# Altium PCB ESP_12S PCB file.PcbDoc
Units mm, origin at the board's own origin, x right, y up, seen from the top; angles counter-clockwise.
Board outline 16 x 24 mm, 4 copper layers (Top Layer, GND, Power, Bottom Layer), stack 0.778 mm thick; 37 components, 28 nets, 113 pads, 121 vias.
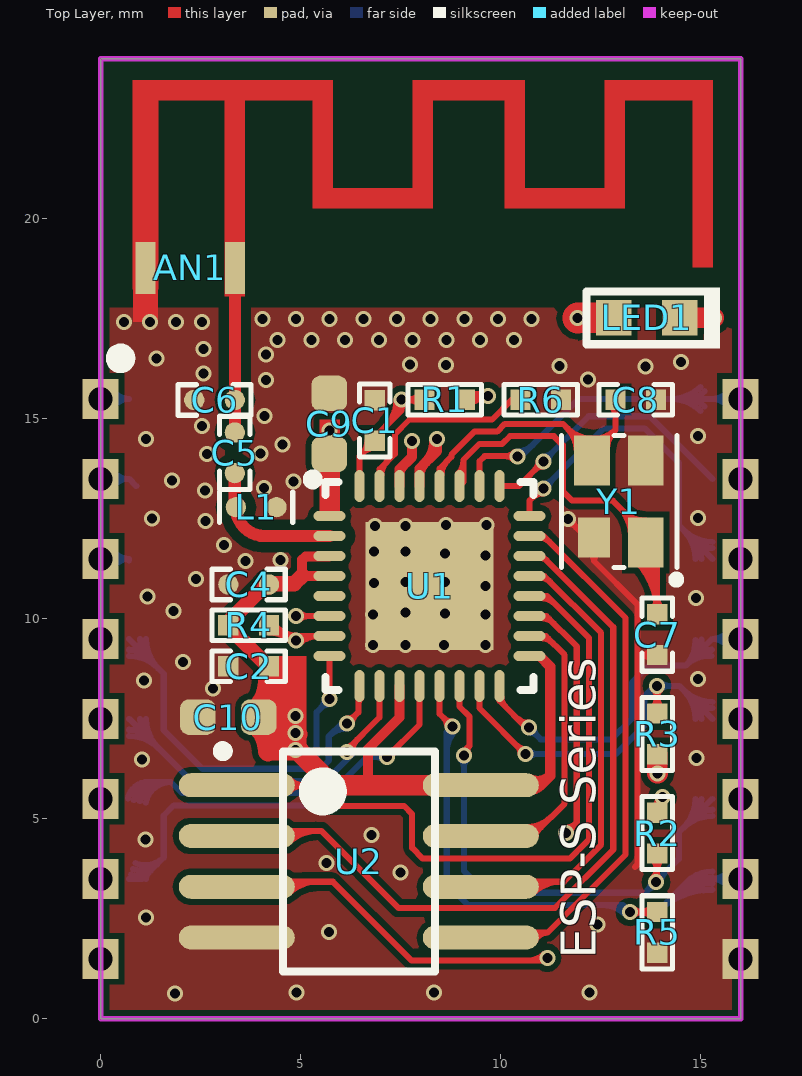
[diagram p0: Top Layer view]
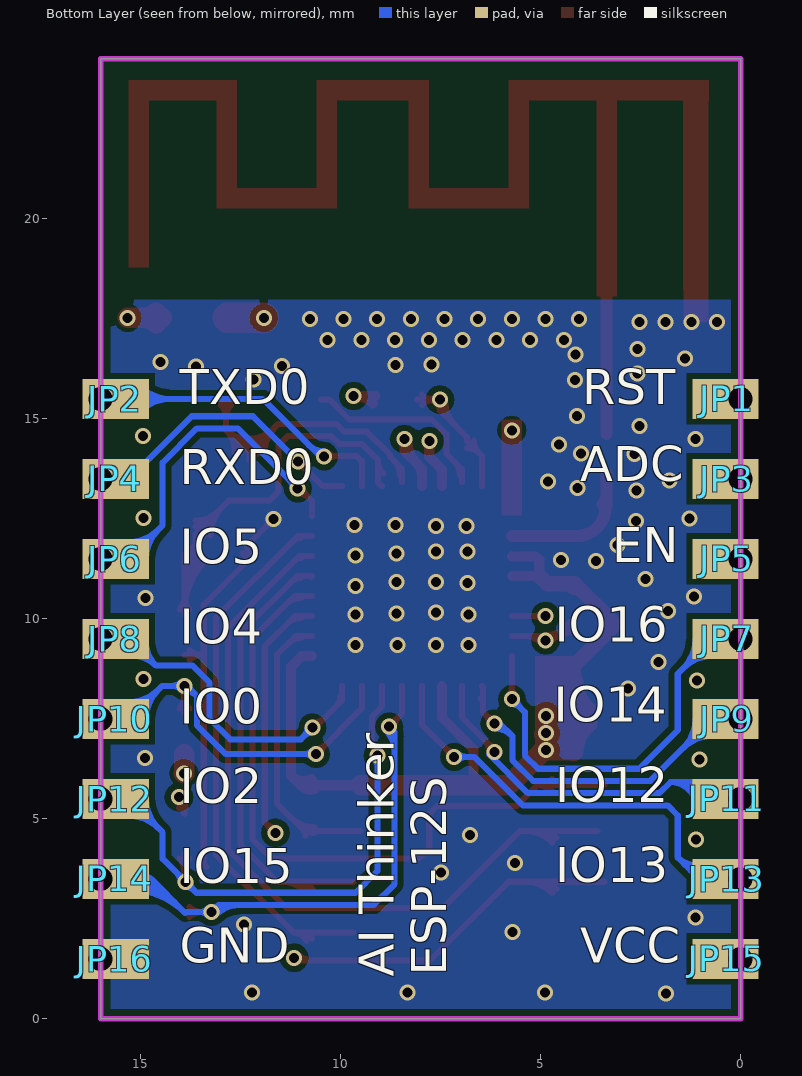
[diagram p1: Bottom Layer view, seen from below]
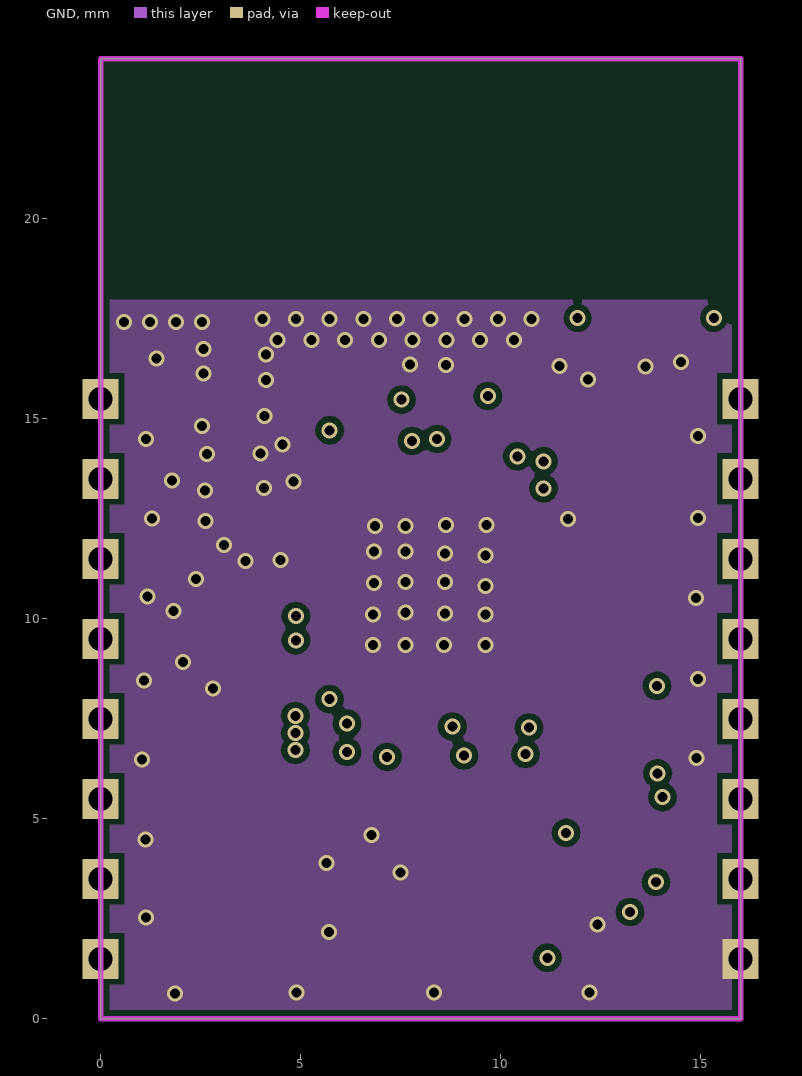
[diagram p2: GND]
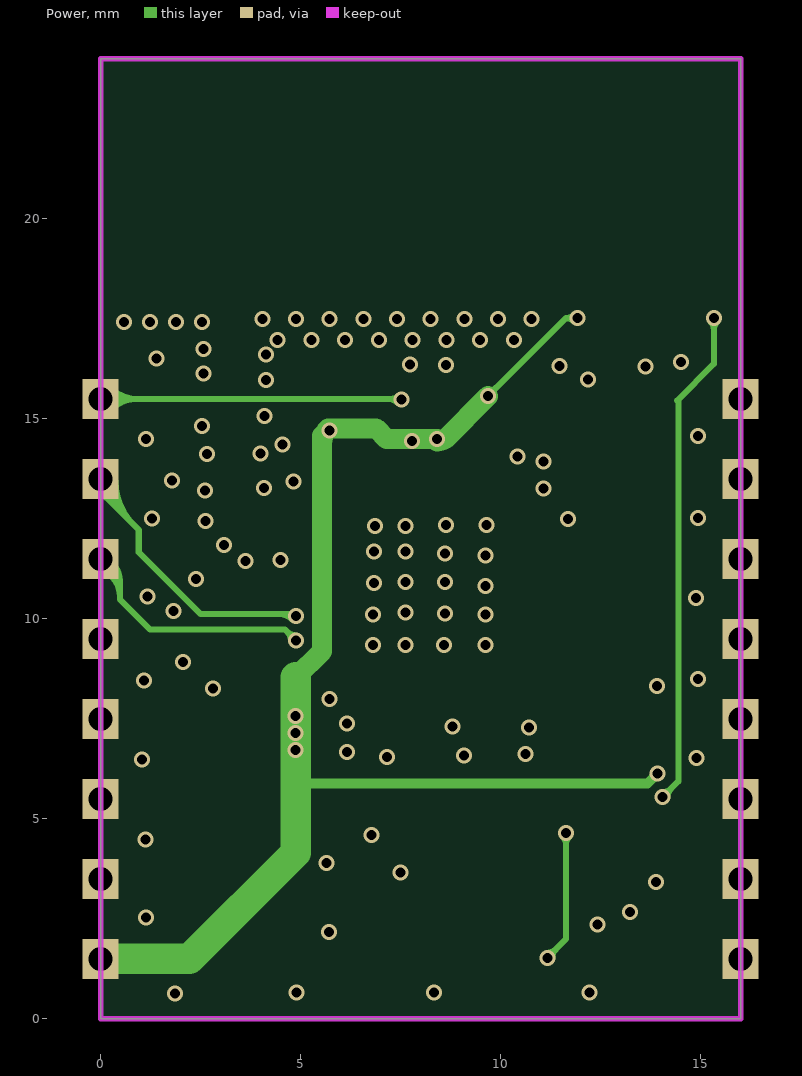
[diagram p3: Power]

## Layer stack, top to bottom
Top Layer: signal copper 0.0356
Dielectric: core 0.254, FR-4, Dk 4.2
GND: signal copper 0.036
Dielectric: prepreg 0.127, Dk 4.2
Power: signal copper 0.036
Dielectric: core 0.254, Dk 4.2
Bottom Layer: signal copper 0.0356

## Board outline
0,0 0,24 16,24 16,0

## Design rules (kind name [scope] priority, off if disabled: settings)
Clearance Clearance_2 [InNet('ANT') or InNet('LAN') vs (InPolygon)] p1: gap=0.254
Clearance Clearance_1 [(InPolygon)] p2: gap=0.152
Clearance [All And Not IsKeepOut vs All And Not IsKeepOut] p3: gap=0.152
ComponentClearance [InNet('No Net')] p1: gap=0.254 collisioncheckmode=3 verticalgap=0.254 showdistances=FALSE
HoleSize [All] p1: absolutevalues=TRUE maxlimit=7.62 minlimit=0 maxpercent=80.000 minpercent=20.000
HoleToHoleClearance [All] p1: gap=0 allowstackedmicrovias=TRUE
MinimumSolderMaskSliver [All] p1: minsoldermaskwidth=0
NetAntennae [InNet('No Net')] p1: netantennaetolerance=0
PolygonConnect [All] p1: connectstyle=Direct reliefconductorwidth=0.254 reliefentries=4 polygonreliefangle="90 Angle"
RoutingVias [All] p1: holewidth=0.711 width=1.27 viastyle="Through Hole" minholewidth=0.025 minwidth=0.127 maxholewidth=0.711 maxwidth=1.27
ShortCircuit ShortCircuit_1 [InNet('ANT') vs InNet('GND')] p1: allowed=TRUE
ShortCircuit [All] p2: allowed=FALSE
SilkToSilkClearance [All] p1: silktosilkclearance=0
SilkscreenOverComponentPads [IsPad] p1: minsilkscreentomaskgap=0
SolderMaskExpansion [All] p1: expansion=0.102
TestPointUsage [All] p1: valid=0 allowmultiple=FALSE
Testpoint [All] p1: side=3 testpointundercomponent=TRUE minsize=1.016 maxsize=2.54 preferedsize=1.524 minholesize=0 maxholesize=1.016 preferedholesize=0.813 testpointgrid=0.025 style=297 order=0-112345678
Width [All] p1: maxlimit=0.762 minlimit=0.152 preferedwidth=0.152
16 further rules are at their usual default settings.

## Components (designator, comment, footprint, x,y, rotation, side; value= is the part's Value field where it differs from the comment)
AN1 "2.4G" ANT1 2.235,18.771 r0 top locked
C1 "1uF" 0402C 6.847,14.956 r0 top
C2 "100nF" 0402C 3.698,8.81 r90 top
C4 "1uF" 0402C_RF 3.698,10.856 r270 top
C5 "8.6pF" 0402C_RF 3.353,14.148 r0 top
C6 "2.4pF" 0402C_RF 2.845,15.469 r270 top
C7 "5.6pF" 0402C 13.909,9.601 r0 top
C8 "5.6pF" 0402C 13.376,15.476 r90 top
C9 "1uF" 0603C 5.715,14.872 r90 top
C10 "10uF" 0603C 3.19,7.54 r0 top
JP1 "Jumper1" PAD 0,15.496 r0 top
JP2 "Jumper1" PAD 16,15.496 r180 top
JP3 "Jumper1" PAD 0,13.496 r0 top
JP4 "Jumper1" PAD 16,13.496 r180 top
JP5 "Jumper1" PAD 0,11.496 r0 top
JP6 "Jumper1" PAD 16,11.496 r180 top
JP7 "Jumper1" PAD 0,9.496 r0 top
JP8 "Jumper1" PAD 16,9.496 r180 top
JP9 "Jumper1" PAD 0,7.496 r0 top
JP10 "Jumper1" PAD 16,7.496 r180 top
JP11 "Jumper1" PAD 0,5.496 r0 top
JP12 "Jumper1" PAD 16,5.496 r180 top
JP13 "Jumper1" PAD 0,3.496 r0 top
JP14 "Jumper1" PAD 16,3.496 r180 top
JP15 "Jumper1" PAD 0,1.496 r0 top
JP16 "Jumper1" PAD 16,1.496 r180 top
L1 "1.5nH" 0402L_RF 3.886,12.789 r90 top
LED1 "Blue" 0603LED 13.652,17.523 r270 top
R1 "12K" 0402R 8.601,15.476 r90 top
R2 "1K" 0402R 13.909,4.64 r180 top
R3 "12K" 0402R 13.909,7.12 r0 top
R4 "12K" 0402R 3.698,9.833 r270 top
R5 "12K" 0402R 13.909,2.159 r0 top
R6 "12K" 0402R 11.001,15.476 r90 top
U1 "ESP8266EX" QFN32 8.22,10.817 r0 top
U2 "W25Q32" WSOP-8 6.452,3.933 r0 top
Y1 "26MHz/10ppm" 3225 12.954,12.929 r180 top

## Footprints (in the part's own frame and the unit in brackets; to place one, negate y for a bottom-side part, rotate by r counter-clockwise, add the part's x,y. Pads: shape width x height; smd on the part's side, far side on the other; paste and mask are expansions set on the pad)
0402C [mil]
  rect 20x20 smd: 1(0,20) 2(0,-20)
  silkscreen extent -15,-36 15,36, body extent -10,-20 10,20, height 20
0402C_RF [mil]
  round 20 smd: 1(0,20) 2(0,-20)
  silkscreen extent -15,-36 15,36, body extent -10,-20 10,20, height 20
0402L_RF [mil]
  round 20 smd: 1(0,20) 2(0,-20)
  silkscreen extent -15,-36 15,36, body extent -13,-19 11,20, height 10
0402R [mil]
  rect 20x20 smd: 1(0,20) 2(0,-20)
  silkscreen extent -15,-36 15,36, body extent -10,-20 10,20, height 20
0603C [mil]
  rrect50% 35x35 smd: 1(-30,0) 2(30,0)
  body extent -38,-18 38,18, height 20
0603LED [mil]
  rect 35x35 smd: 1(0,-32.5) 2(0,32.5)
  silkscreen extent -30,-59 30,72, body extent -24,-39 24,40, height 39
3225 [mm] "Quartz Crystal, SM; Body 3.2 x 2.5 mm"
  rect 0.896x1.248 smd: 1(-0.673,1.024) 2(-0.673,-1.024) 3(0.673,-1.024)
  rect 0.794x0.994 smd: 4(0.622,0.897)
  silkscreen extent -1.53,-1.65 1.43,2.05, body extent -1.27,-1.6 1.23,1.6, height 0.81
ANT1 [mm]
  rect 0.5x1.3 smd: 1(1.118,0) 2(-1.118,0)
  Top Layer region: -1.431,4.188 -1.431,4.688 3.569,4.688 3.569,1.988 5.569,1.988 5.569,4.688 8.369,4.688 8.369,1.988 10.369,1.988 10.369,4.688 13.069,4.688 13.069,0.015 12.569,0.015 12.569,4.188 10.869,4.188 10.869,1.488 7.869,1.488 7.869,4.188 6.069,4.188 6.069,1.488 3.069,1.488 3.069,4.188 1.369,4.188 1.369,-0.712 0.869,-0.712 0.869,4.188
  Top Layer region: -1.429,4.62 -1.429,-0.533 -0.802,-0.533 -0.802,4.62
PAD [mm]
  rect 0.9x1 hole 0.6: 1(0,0)
  rect 1x1 smd far side: 1(0.71,0)
QFN32 [mm]
  oval 0.8x0.25 smd: 1(-2.5,1.75) 2(-2.5,1.25) 3(-2.5,0.75) 4(-2.5,0.25) 5(-2.5,-0.25) 6(-2.5,-0.75) 7(-2.5,-1.25) 8(-2.5,-1.75) 17(2.5,-1.75) 18(2.5,-1.25) 19(2.5,-0.75) 20(2.5,-0.25) 21(2.5,0.25) 22(2.5,0.75) 23(2.5,1.25) 24(2.5,1.75)
  oval 0.25x0.8 smd: 9(-1.75,-2.5) 10(-1.25,-2.5) 11(-0.75,-2.5) 12(-0.25,-2.5) 13(0.25,-2.5) 14(0.75,-2.5) 15(1.25,-2.5) 16(1.75,-2.5) 25(1.75,2.5) 26(1.25,2.5) 27(0.75,2.5) 28(0.25,2.5) 29(-0.25,2.5) 30(-0.75,2.5) 31(-1.25,2.5) 32(-1.75,2.5)
  rect 3.2x3.2 smd paste-2.54: 33(0,0)
  silkscreen extent -3.04,-2.6 2.6,2.79, body extent -2.51,-2.51 2.51,2.51, height 0.8
WSOP-8 [mm]
  oval 2.9x0.6 smd: 1(-3.05,1.905) 2(-3.05,0.635) 3(-3.05,-0.635) 4(-3.05,-1.905) 5(3.05,-1.905) 6(3.05,-0.635) 7(3.05,0.635) 8(3.05,1.905)
  silkscreen extent -3.52,-2.75 1.9,2.88, body extent -4.05,-2.73 4.05,2.73, height 1.75

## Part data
AN1: library part Antenna, "2.4G PCB Antenna"
C1 C2 C7 C8: library part C0402, "Capacitor"
C4 C5 C6 C9 C10: library part CAP
L1: library part LL
LED1: library part LED
R1 R2 R3 R4 R5 R6: library part R0402, "Resistor"
U1: library part ESP8266
U2: library part W25QXX
Y1: library part XTAL3

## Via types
v1: diameter 0.4, hole 0.25, Top Layer to Bottom Layer, tented both sides, 121 vias

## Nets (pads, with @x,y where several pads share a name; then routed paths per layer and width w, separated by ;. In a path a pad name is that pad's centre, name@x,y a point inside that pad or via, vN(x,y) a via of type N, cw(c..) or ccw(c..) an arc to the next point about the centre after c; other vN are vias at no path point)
#RESET: C1.2 JP1.1 R1.1 U1.32 | length 19
  Top Layer w0.152: U1.32 6.47,14.071 C1.2 6.847,14.539 7.521,15.213 ; C1.2@6.669,14.448 cw(c6.24,14.448) 6.543,14.145 cw(c6.847,13.841) C1.2@6.847,14.271 ; 7.123,14.815 ccw(c6.462,15.476) v1@7.397,15.476 ; 7.383,15.075 ccw(c6.983,15.476) v1@7.549,15.476 ; v1@7.442,15.381 cw(c7.303,15.213) 7.521,15.213 ; v1@7.442,15.469 v1@7.45,15.476 ; v1@7.6,15.381 ccw(c7.739,15.213) 7.521,15.213 ; v1@7.608,15.389 cw(c7.82,15.177) 7.82,15.476 cw(c7.82,15.775) v1@7.608,15.564 ; R1.1@7.967,15.35 ccw(c7.663,15.047) 7.663,15.476 ccw(c7.663,15.905) R1.1@7.967,15.602 ; R1.1 v1(7.521,15.476) 7.521,15.213
  Power w0.152: JP1.1@0.14,15.496 v1@7.415,15.496 ; JP1.1@0.157,15.339 cw(c0.535,14.961) 0.535,15.496 cw(c0.535,16.03) JP1.1@0.157,15.652 ; JP1.1@0.264,15.231 cw(c0.902,14.593) 0.902,15.496 cw(c0.902,16.398) JP1.1@0.264,15.76 ; 7.175,15.496 cw(c7.175,15.13) v1@7.433,15.389 ; 7.269,15.496 ccw(c7.269,15.728) v1@7.433,15.564
  Bottom Layer w0.152: JP1.1@0.308,15.284 cw(c0.71,15.008) JP1.1@0.71,15.496 ; JP1.1@0.308,15.707 ccw(c0.71,15.983) JP1.1@0.71,15.496 ; JP1.1@0.337,15.294 ccw(c0,15.113) JP1.1@0,15.496 ; JP1.1@0.337,15.697 cw(c0,15.878) JP1.1@0,15.496 ; JP1.1@0,15.496 JP1.1@0.71,15.496
ADC: JP3.1 U1.6 | length 14
  Top Layer w0.152: v1(4.877,10.066) U1.6 ; v1@4.964,9.979 cw(c5.176,9.768) 5.176,10.066 cw(c5.176,10.365) v1@4.964,10.154
  Power w0.152: JP3.1@0,13.072 cw(c0,12.824) JP3.1@0.175,12.999 ; JP3.1@0.069,13.445 ccw(c0.869,13.437) 0.303,12.871 ; JP3.1@0.14,13.496 0.14,13.035 0.952,12.222 0.952,11.663 2.493,10.122 v1@4.877,10.122 ; JP3.1@0.221,13.443 ccw(c1.377,13.432) 0.56,12.615 ; JP3.1@0.374,13.442 ccw(c1.885,13.427) 0.816,12.358 ; 4.444,10.122 cw(c4.444,9.634) v1@4.789,9.979
  Bottom Layer w0.152: JP3.1@0.318,13.299 cw(c0.671,13.08) JP3.1@0.671,13.496 ; JP3.1@0.318,13.693 ccw(c0.671,13.912) JP3.1@0.671,13.496 ; JP3.1@0.337,13.294 ccw(c0,13.113) JP3.1@0,13.496 ; JP3.1@0.337,13.697 cw(c0,13.878) JP3.1@0,13.496 ; JP3.1@0.71,13.496 JP3.1@0.889,13.317 ; v1@4.864,10.135 v1@4.877,10.122 ; JP3.1@0,13.496 JP3.1@0.671,13.496
ANT: AN1.1 C5.1 C6.1 | length 4.2
  Top Layer w0.305: C5.1@3.353,14.615 AN1.1
CLK: U1.21 U2.6 | length 12.4
  Top Layer w0.152: U2.6@9.68,3.425 11.582,3.425 12.51,4.353 12.51,9.648 11.091,11.067 U1.21 U1.21@10.737,11.049 ; U2.6@10.703,3.248 cw(c11.131,2.819) 11.131,3.425 ; U2.6@10.811,3.14 cw(c11.499,2.451) 11.499,3.425 ; U1.21@10.995,11.018 cw(c10.995,10.668) 11.242,10.915
CS: U1.20 U2.1 | length 18.7
  Top Layer w0.152: U2.1 5.084,5.838 ; U2.1@4.712,5.682 cw(c5.084,5.319) 5.084,5.838 ; U2.1@4.712,5.995 ccw(c5.084,6.357) 5.084,5.838 ; U1.20 11.16,10.567 12.205,9.521 12.205,4.479 11.73,4.005 8.052,4.005 7.786,4.27 7.786,5.117 7.582,5.321 5.601,5.321 5.084,5.838 ; U1.20@10.995,10.518 cw(c10.995,10.001) 11.36,10.367 ; U1.20@11.016,10.523 cw(c11.102,10.344) 11.242,10.484
D0: U1.22 U2.2 | length 20.4
  Top Layer w0.152: U2.2@3.58,4.695 5.516,4.695 7.442,2.77 11.357,2.77 12.814,4.227 12.814,9.792 11.04,11.567 U1.22 ; U2.2@4.603,4.518 cw(c5.031,4.089) 5.031,4.695 ; U2.2@4.711,4.41 cw(c5.399,3.721) 5.399,4.695 ; U1.22@10.995,11.518 cw(c10.995,11.292) 11.155,11.452
D1: U1.23 U2.5 | length 14.3
  Top Layer w0.152: U2.5@9.68,2.155 11.174,2.155 13.119,4.101 13.119,10.02 11.073,12.067 U1.23 U1.23 ; U2.5@10.718,2.001 cw(c10.947,1.908) 10.947,2.155 ; U2.5@10.86,1.944 cw(c11.174,1.816) 11.174,2.155 ; U1.23@10.995,12.018 cw(c10.995,11.711) 11.212,11.928
EN: JP5.1 R4.1 U1.7 | length 15.7
  Top Layer w0.152: R4.1@4.206,9.655 cw(c4.206,8.866) v1@4.765,9.424 ; R4.1@4.206,9.808 cw(c4.206,9.386) 4.504,9.684 ; R4.1@4.206,9.915 4.274,9.915 4.727,9.461 v1(4.877,9.461) 4.982,9.567 U1.7 ; R4.1@4.41,9.778 ccw(c4.877,10.245) v1@4.877,9.585 ; 4.67,9.518 ccw(c4.877,9.725) v1@4.877,9.433 ; v1@4.857,9.481 cw(c5.062,9.276) 5.062,9.567 ; v1@4.964,9.374 cw(c5.43,8.908) U1.7@5.43,9.567
  Power w0.152: JP5.1@-0.051,11.23 cw(c-0.209,10.557) 0.483,10.557 ; JP5.1@-0.016,11.378 cw(c-0.164,10.749) 0.483,10.749 ; JP5.1@0.019,11.527 cw(c-0.118,10.942) 0.483,10.942 ; JP5.1@0.14,11.496 0.14,11.328 0.483,10.986 0.483,10.478 1.233,9.728 4.609,9.728 v1(4.877,9.461) ; 4.664,9.673 ccw(c4.877,9.886) v1@4.877,9.585 ; 4.666,9.671 cw(c4.456,9.461) v1@4.753,9.461
  Bottom Layer w0.152: JP5.1@0.308,11.284 cw(c0.71,11.008) JP5.1@0.71,11.496 ; JP5.1@0.308,11.707 ccw(c0.71,11.983) JP5.1@0.71,11.496 ; JP5.1@0.337,11.294 ccw(c0,11.113) JP5.1@0,11.496 ; JP5.1@0.337,11.697 cw(c0,11.878) JP5.1@0,11.496 ; JP5.1@0.71,11.457 JP5.1@0.71,11.496 ; JP5.1@0,11.496 JP5.1@0.71,11.496
GND: AN1.2 C1.1 C2.1 C4.2 C6.2 C7.2 C8.2 C9.2 C10.1 JP16.1 L1.2 R5.2 R6.2 U1.33 U2.4 Y1.2 Y1.4 | length 11.5
  Top Layer w0.152: v1@11.678,12.373 cw(c11.678,12.074) 11.889,12.285 cw(c12.1,12.497) v1@11.801,12.497 ; v1(11.678,12.497) 12.332,11.843 12.332,11.443 ; Y1.4@12.204,11.638 cw(c12.119,11.443) 12.332,11.443 ; Y1.4@12.46,11.638 ccw(c12.545,11.443) 12.332,11.443 ; 13.36,3.797 13.424,3.861 13.424,10.351 12.332,11.443 ; 13.449,9.093 C7.2 ; C7.2@13.784,8.967 ccw(c13.48,8.664) 13.48,9.093 ccw(c13.48,9.522) C7.2@13.784,9.219
  other v1: 1.862,0.631 4.892,0.65 8.329,0.65 12.214,0.65 5.706,2.167 12.421,2.353 1.133,2.53 7.498,3.654 5.648,3.896 1.123,4.486 6.764,4.599 1.031,6.478 14.889,6.52 2.812,8.251 1.087,8.459 14.936,8.498 2.061,8.914 6.806,9.343 7.619,9.343 8.584,9.343 9.625,9.343 6.806,10.105 9.625,10.105 8.609,10.13 7.619,10.155 1.816,10.188 14.879,10.519 1.171,10.561 9.625,10.816 6.831,10.892 7.619,10.917 8.609,10.917 2.384,10.994 3.616,11.44 4.493,11.466 9.625,11.578 8.609,11.629 6.831,11.679 7.619,11.679 3.078,11.849 6.857,12.314 7.619,12.314 8.635,12.34 9.651,12.34 2.62,12.439 1.284,12.503 14.936,12.516 2.603,13.209 4.086,13.262 4.82,13.434 1.785,13.456 2.654,14.122 3.995,14.135 4.547,14.355 1.127,14.489 14.938,14.572 2.531,14.818 4.092,15.067 4.137,15.963 12.185,15.984 2.575,16.13 13.622,16.306 11.466,16.322 7.73,16.358 8.626,16.345 14.501,16.413 1.397,16.508 4.131,16.6 2.575,16.746 4.422,16.962 5.266,16.962 6.11,16.962 6.954,16.962 7.798,16.962 8.642,16.962 9.486,16.962 10.33,16.962 0.587,17.413 1.235,17.413 1.883,17.413 2.53,17.413 4.041,17.499 4.883,17.499 5.724,17.499 6.565,17.499 7.406,17.499 8.248,17.499 9.089,17.499 9.93,17.499 10.771,17.499
IO0: JP10.1 R3.1 U1.15 | length 14.6
  Top Layer w0.152: U1.15 9.47,7.764 v1(10.617,6.617) ; v1@10.493,6.617 ccw(c10.195,6.617) 10.406,6.828 ccw(c10.617,7.039) v1@10.617,6.741 ; R3.1@13.784,7.754 ccw(c13.48,8.058) 13.909,8.058 ccw(c14.338,8.058) R3.1@14.035,7.754 ; v1@13.822,8.234 cw(c13.61,8.022) 13.909,8.022 cw(c14.208,8.022) v1@13.997,8.234 ; R3.1 v1(13.909,8.321)
  Bottom Layer w0.152: v1(10.617,6.617) 12.878,6.617 13.589,7.328 13.589,8.065 13.846,8.321 v1(13.909,8.321) 14.464,8.321 JP10.1@15.29,7.496 ; v1@10.705,6.529 cw(c10.916,6.318) 10.916,6.617 cw(c10.916,6.916) v1@10.705,6.704 ; 13.59,8.065 cw(c13.909,7.745) v1@13.909,8.197 ; v1@13.997,8.234 cw(c14.208,8.022) 14.208,8.321 cw(c14.208,8.62) v1@13.997,8.409 ; JP10.1@14.866,7.496 ccw(c13.843,7.496) 14.567,8.219 ccw(c15.29,8.943) JP10.1@15.29,7.919 ; JP10.1@15.019,7.496 ccw(c14.363,7.496) 14.827,7.959 ccw(c15.29,8.422) JP10.1@15.29,7.767
IO2: JP12.1 R2.1 U1.14 | length 18.6
  Top Layer w0.152: U1.14 8.97,7.804 9.217,7.557 9.217,6.82 ; v1@9.081,6.683 9.217,6.82 ; v1@9.19,6.637 cw(c9.327,6.71) 9.217,6.82 ; R2.1@13.784,4.006 cw(c13.48,3.702) 13.909,3.702 cw(c14.338,3.702) R2.1@14.035,4.006 ; v1@13.794,3.504 ccw(c13.514,3.783) 13.909,3.783 ; v1(13.881,3.416) 13.909,3.444 R2.1 ; 13.909,3.647 ccw(c14.112,3.647) v1@13.969,3.504
  Bottom Layer w0.152: v1@8.993,6.491 cw(c8.782,6.28) 9.081,6.28 cw(c9.379,6.28) v1@9.168,6.491 ; v1(9.081,6.579) 9.081,3.696 9.627,3.15 13.607,3.15 14.453,3.995 14.453,4.658 JP12.1@15.29,5.496 ; 13.657,3.2 cw(c13.881,2.976) v1@13.881,3.293 ; 13.675,3.217 ccw(c13.476,3.416) v1@13.757,3.416 ; v1@13.881,3.54 ccw(c13.881,3.822) 14.08,3.623 ; v1@14.005,3.416 cw(c14.321,3.416) 14.098,3.64 ; JP12.1@14.866,5.496 cw(c13.843,5.496) 14.567,4.772 cw(c15.29,4.049) JP12.1@15.29,5.072 ; JP12.1@15.019,5.496 cw(c14.363,5.496) 14.827,5.032 cw(c15.29,4.569) JP12.1@15.29,5.224
IO4: JP8.1 U1.16 | length 12.6
  Top Layer w0.152: U1.16 9.97,7.95 10.643,7.277 v1(10.706,7.277) ; U1.16@10.018,8.041 ccw(c10.357,8.041) 10.118,7.802 ; 10.386,7.533 ccw(c10.706,7.853) v1@10.706,7.401
  Bottom Layer w0.152: v1@10.706,7.153 cw(c10.706,6.854) 10.917,7.066 cw(c11.129,7.277) v1@10.83,7.277 ; v1(10.706,7.277) 10.998,6.985 12.764,6.985 13.284,7.506 13.284,8.407 13.703,8.827 14.621,8.827 ; JP8.1@14.867,9.472 cw(c14.024,9.424) 14.621,8.827 ; JP8.1@15.019,9.48 cw(c14.479,9.45) 14.862,9.067 cw(c15.244,8.685) JP8.1@15.275,9.225 ; JP8.1@15.266,9.072 ccw(c15.218,8.229) 14.621,8.827 ; JP8.1@15.692,9.284 ccw(c15.29,9.008) JP8.1@15.29,9.496 ; JP8.1@15.692,9.707 cw(c15.29,9.983) JP8.1@15.29,9.496 ; JP8.1@15.86,9.496 JP8.1@15.29,9.496 ; 14.621,8.827 JP8.1@15.29,9.496
IO5: JP6.1 U1.24 | length 11.6
  Top Layer w0.152: U1.24 10.72,12.955 11.024,13.259 v1(11.074,13.259) ; 10.776,13.012 cw(c11.074,12.713) v1@11.074,13.135 ; 10.899,13.134 ccw(c10.774,13.259) v1@10.951,13.259
  Bottom Layer w0.152: v1(11.074,13.259) 12.573,14.757 13.597,14.757 14.453,13.902 14.453,12.333 JP6.1@15.29,11.496 ; v1@11.074,13.383 ccw(c11.074,13.681) 11.286,13.47 ccw(c11.497,13.259) v1@11.198,13.259 ; JP6.1@14.866,11.496 ccw(c13.843,11.496) 14.567,12.219 ccw(c15.29,12.943) JP6.1@15.29,11.919 ; JP6.1@15.019,11.496 ccw(c14.363,11.496) 14.827,11.959 ccw(c15.29,12.422) JP6.1@15.29,11.767
IO9: U1.18 U2.7 | length 8.9
  Top Layer w0.152: U2.7@9.502,4.695 10.914,4.695 11.595,5.377 11.595,9.096 11.125,9.567 U1.18 ; U2.7@10.652,4.64 ccw(c10.652,5.136) 11.004,4.785 ; U2.7@10.652,4.792 ccw(c10.652,5.657) 11.264,5.045 ; U2.7@10.876,4.568 cw(c11.092,4.568) 10.939,4.721 ; U1.18@10.995,9.518 cw(c10.995,9.086) 11.3,9.391 ; U1.18@11.019,9.524 cw(c11.089,9.402) 11.189,9.502
IO10: U1.19 U2.3 | length 21.8
  Top Layer w0.152: U2.3@3.402,3.425 5.804,3.425 7.769,1.461 11.1,1.461 v1(11.163,1.524) ; U2.3@4.603,3.248 cw(c5.031,2.819) 5.031,3.425 ; U2.3@4.711,3.14 cw(c5.399,2.451) 5.399,3.425 ; 10.711,1.461 ccw(c10.711,1.976) v1@11.076,1.612 ; U1.19 11.142,10.067 11.9,9.309 11.9,4.915 v1(11.633,4.648) ; U1.19@10.995,10.018 cw(c10.995,9.543) 11.33,9.879 ; U1.19@11.017,10.023 cw(c11.096,9.872) 11.216,9.993 ; v1@11.633,4.772 ccw(c11.633,5.071) 11.845,4.86 ccw(c12.056,4.648) v1@11.757,4.648
  Power w0.152: v1(11.163,1.524) 11.633,1.994 v1(11.633,4.648) ; v1@11.163,1.648 ccw(c11.163,1.947) 11.375,1.735 ccw(c11.586,1.524) v1@11.287,1.524 ; v1@11.546,4.561 cw(c11.334,4.349) 11.633,4.349 cw(c11.932,4.349) v1@11.721,4.561
IO12: JP11.1 U1.10 | length 11.3
  Top Layer w0.152: v1(6.16,6.668) 6.16,6.723 6.97,7.534 U1.10 ; v1@6.16,6.791 ccw(c6.16,6.955) 6.275,6.839 ; v1@6.283,6.668 cw(c6.717,6.668) 6.41,6.974
  Bottom Layer w0.152: JP11.1@0.677,5.502 cw(c1.189,5.395) JP11.1@1.189,5.918 ; JP11.1@0.826,5.471 cw(c1.377,5.356) 1.377,5.918 ; JP11.1@0.976,5.44 cw(c1.565,5.316) 1.565,5.918 ; JP11.1@1.125,5.409 cw(c1.753,5.277) 1.753,5.918 ; JP11.1@1.133,5.918 1.753,5.918 ; v1@6.291,6.61 5.319,5.639 2.032,5.639 1.753,5.918
IO13: JP13.1 U1.12 | length 13.5
  Top Layer w0.152: v1(7.163,6.546) 7.97,7.353 U1.12 ; v1@7.163,6.67 ccw(c7.163,6.969) 7.374,6.757 ccw(c7.585,6.546) v1@7.287,6.546
  Bottom Layer w0.152: JP13.1@0.71,3.496 1.04,3.496 1.575,4.031 ; JP13.1@0.755,3.606 ccw(c0.927,4.029) 1.25,3.706 ; JP13.1@0.812,3.747 ccw(c1.021,4.26) 1.412,3.868 ; JP13.1@0.87,3.888 ccw(c1.115,4.491) 1.575,4.031 ; JP13.1@1.134,3.496 cw(c1.361,3.496) JP13.1@1.2,3.656 ; v1@7.075,6.458 ccw(c6.864,6.247) 6.864,6.546 ccw(c6.864,6.845) v1@7.075,6.633 ; v1(7.163,6.546) 6.664,6.546 6.215,6.097 6.209,6.097 5.445,5.334 1.829,5.334 1.575,5.08 1.575,4.031
IO14: JP9.1 U1.9 | length 11.9
  Top Layer w0.152: v1(6.16,7.379) 6.443,7.662 6.443,8.29 U1.9 ; v1@6.16,7.503 ccw(c6.16,7.801) 6.371,7.59 ccw(c6.582,7.379) v1@6.283,7.379 ; 6.443,7.859 cw(c6.652,7.859) U1.9@6.504,8.007
  Bottom Layer w0.152: JP9.1@0.71,7.072 cw(c0.71,6.049) 1.433,6.772 cw(c2.157,7.496) JP9.1@1.134,7.496 ; JP9.1@0.71,7.224 cw(c0.71,6.569) 1.173,7.032 cw(c1.637,7.496) JP9.1@0.981,7.496 ; JP9.1@0.71,7.496 2.262,5.944 5.193,5.944 5.702,6.452 5.702,7.06 6.02,7.379 v1(6.16,7.379) ; 5.71,7.069 cw(c6.16,6.619) v1@6.16,7.255
IO15: JP14.1 R5.1 U1.13 | length 24.2
  Top Layer w0.152: U1.13 8.47,7.621 v1(8.788,7.303) v1@8.788,7.309 ; v1@8.665,7.303 ccw(c8.366,7.303) 8.577,7.514 ccw(c8.788,7.725) v1@8.788,7.426 ; v1(13.233,2.667) R5.1 ; v1@13.321,2.579 cw(c13.532,2.368) 13.532,2.667 cw(c13.532,2.966) v1@13.321,2.755 ; R5.1@13.784,2.541 ccw(c13.48,2.238) 13.48,2.667 ccw(c13.48,3.096) R5.1@13.784,2.793
  Bottom Layer w0.152: 8.652,6.674 cw(c9.417,6.674) v1@8.876,7.215 ; 8.652,7.042 cw(c9.049,7.042) v1@8.768,7.323 ; v1@8.788,7.309 v1(8.788,7.303) 8.652,7.166 8.652,3.364 9.171,2.845 9.982,2.845 13.056,2.845 v1(13.233,2.667) 13.907,2.667 14.735,3.496 JP14.1@15.29,3.496 ; 12.505,2.845 cw(c12.505,1.939) v1@13.146,2.579 ; 12.873,2.845 cw(c12.873,2.307) v1@13.254,2.687 ; v1@13.321,2.579 cw(c13.532,2.368) 13.532,2.667 cw(c13.532,2.966) v1@13.321,2.755 ; 13.887,2.648 cw(c15.279,1.257) JP14.1@15.289,3.224 ; 14.146,2.906 cw(c15.281,1.771) JP14.1@15.289,3.377 ; 14.404,3.165 cw(c15.284,2.285) JP14.1@15.29,3.529 ; 14.662,3.423 cw(c15.286,2.799) JP14.1@15.291,3.681 ; JP14.1@15.663,3.294 cw(c16,3.113) JP14.1@16,3.496 ; JP14.1@15.663,3.697 ccw(c16,3.878) JP14.1@16,3.496 ; JP14.1@15.692,3.284 ccw(c15.29,3.008) JP14.1@15.29,3.496 ; JP14.1@15.692,3.707 cw(c15.29,3.983) JP14.1@15.29,3.496 ; JP14.1@15.29,3.496 JP14.1@16,3.496
IO16: JP7.1 U1.8 | length 13.2
  Top Layer w0.152: v1@5.632,8.076 ccw(c5.421,8.287) 5.72,8.287 ccw(c6.019,8.287) v1@5.807,8.076 ; v1(5.72,7.988) U1.8
  Bottom Layer w0.152: JP7.1@0.71,9.072 cw(c0.71,8.067) 1.421,8.777 ; JP7.1@0.71,9.224 cw(c0.71,8.587) JP7.1@1.161,9.038 ; JP7.1@0.71,9.496 0.71,9.488 1.575,8.623 1.575,7.214 2.54,6.248 5.067,6.248 5.397,6.579 5.397,7.665 v1(5.72,7.988) ; JP7.1@0.981,9.496 ccw(c1.655,9.496) JP7.1@1.179,9.02 ; JP7.1@1.134,9.496 ccw(c2.175,9.496) 1.439,8.759 ; v1@5.596,7.988 cw(c5.297,7.988) 5.508,7.777 cw(c5.72,7.566) v1@5.72,7.865
LAN: C5.2 L1.1 U1.2 | length 3.9
  Top Layer w0.305: 3.353,13.095 ccw(c3.685,13.095) L1.1@3.45,12.861 ; C5.2 3.353,12.814 ccw(c3.378,12.814) L1.1 ccw(c4.101,12.789) 4.101,12.067 U1.2
NetC7_1: C7.1 U1.27 Y1.1 | length 16.3
  Top Layer w0.152: U1.27@8.935,13.626 ccw(c8.61,13.951) 9.07,13.951 ; U1.27 9.07,13.417 9.07,13.971 9.47,14.371 10.037,14.371 10.232,14.567 11.328,14.567 11.553,14.342 11.553,13.187 11.786,12.954 12.802,12.954 13.627,12.129 Y1.1 ; 12.958,12.797 cw(c12.242,12.081) Y1.1@13.255,12.081 ; 13.074,12.681 ccw(c13.627,13.234) Y1.1@13.627,12.452 ; 13.219,12.537 cw(c12.762,12.081) Y1.1@13.408,12.081 ; Y1.1@13.334,12.421 ccw(c13.627,12.714) Y1.1@13.627,12.3 ; Y1.1@13.364,11.466 cw(c12.048,10.15) C7.1@13.909,10.15 ; Y1.1@13.472,11.574 cw(c12.416,10.518) 13.909,10.518 ; Y1.1@13.58,11.682 cw(c12.784,10.886) 13.909,10.886 ; Y1.1@13.687,11.789 cw(c13.152,11.254) 13.909,11.254 ; C7.1@13.784,10.235 ccw(c13.48,10.538) 13.909,10.538 ccw(c14.338,10.538) C7.1@14.035,10.235 ; C7.1 Y1.1@13.909,11.623
NetC8_1: C8.1 U1.28 Y1.3 | length 11.8
  Top Layer w0.152: U1.28@8.47,13.418 8.47,13.752 8.765,14.047 8.765,14.098 9.344,14.676 9.911,14.676 10.106,14.872 11.557,14.872 11.944,14.485 Y1.3@11.944,14.214 ; U1.28@8.518,13.592 cw(c9.023,13.592) 8.666,13.948 ; 11.633,14.796 cw(c10.964,14.128) Y1.3@11.909,14.128 ; 11.68,14.749 ccw(c12.281,15.351) Y1.3@12.281,14.5 ; Y1.3@11.893,14.536 cw(c11.485,14.128) Y1.3@12.062,14.128 ; Y1.3@11.94,14.489 ccw(c12.281,14.83) Y1.3@12.281,14.348 ; Y1.3 12.281,14.135 12.868,14.722 ; Y1.3@12.29,14.347 ccw(c12.309,14.79) Y1.3@12.623,14.477 ; Y1.3@12.297,14.5 ccw(c12.329,15.261) 12.868,14.722 ; Y1.3@12.5,14.142 cw(c12.943,14.17) Y1.3@12.629,14.483 ; Y1.3@12.652,14.151 cw(c13.392,14.198) 12.868,14.722 ; C8.1@12.742,15.35 cw(c12.439,15.047) 12.868,15.047 cw(c13.297,15.047) C8.1@12.994,15.35 ; C8.1 12.868,14.722
NetLED1_2: LED1.2 R2.2 | length 16.7
  Top Layer w0.152: R2.2@13.909,5.124 cw(c14.244,5.124) v1@14.1,5.426 ; R2.2 13.909,5.401 v1(14.047,5.538) ccw(c14.185,5.4) R2.2@14.04,5.268 ; R2.2@13.909,5.366 cw(c14.129,5.366) v1@14.034,5.564 ; R2.2@13.928,5.165 cw(c14.067,5.292) v1@13.934,5.425
  Top Layer w0.508: LED1.2 v1(15.329,17.523) ; LED1.2@14.613,17.388 cw(c14.938,17.063) 14.938,17.523 cw(c14.938,17.983) LED1.2@14.613,17.658
  Power w0.152: v1(14.047,5.538) 14.441,5.933 14.441,15.423 14.411,15.453 15.329,16.371 v1(15.329,17.523) ; v1@14.047,5.662 ccw(c14.047,5.961) 14.258,5.749 ccw(c14.469,5.538) v1@14.17,5.538 ; v1@15.242,17.435 cw(c15.031,17.224) 15.329,17.224 cw(c15.628,17.224) v1@15.417,17.435
NetR6_1: R6.1 U1.31 | length 5.2
  Top Layer w0.152: U1.31@6.97,13.418 6.97,13.738 7.357,14.125 7.357,14.617 7.72,14.981 9.783,14.981 10.278,15.476 R6.1 ; U1.31@7.018,13.592 cw(c7.49,13.592) 7.157,13.925
RX: JP4.1 U1.25 | length 7.6
  Top Layer w0.152: U1.25 10.45,13.317 v1(11.07,13.937) ; v1@10.946,13.937 cw(c10.647,13.937) 10.858,13.725 cw(c11.07,13.514) v1@11.07,13.813
  Bottom Layer w0.152: v1(11.07,13.937) 12.195,15.062 13.723,15.062 JP4.1@15.29,13.496 ; v1@11.07,14.06 ccw(c11.07,14.359) 11.281,14.148 ccw(c11.492,13.937) v1@11.194,13.937
TX: JP2.1 U1.26 | length 13.1
  Top Layer w0.152: U1.26 9.47,13.94 9.596,14.067 10.409,14.067 v1(10.414,14.061) v1@10.414,14.046 ; 10.103,14.067 cw(c10.103,13.75) v1@10.326,13.974 ; 10.127,14.067 ccw(c10.127,14.348) v1@10.326,14.149
  Bottom Layer w0.152: v1@10.414,14.046 10.502,14.046 11.952,15.496 JP2.1@15.29,15.496 ; v1@10.414,14.185 ccw(c10.414,14.734) 10.802,14.346 ; JP2.1@14.99,15.196 ccw(c14.267,14.472) 14.267,15.496 ccw(c14.267,16.519) JP2.1@14.99,15.795 ; JP2.1@15.098,15.304 ccw(c14.635,14.84) 14.635,15.496 ccw(c14.635,16.151) JP2.1@15.098,15.688 ; JP2.1@15.663,15.294 cw(c16,15.113) JP2.1@16,15.496 ; JP2.1@15.663,15.697 ccw(c16,15.878) JP2.1@16,15.496 ; JP2.1@15.692,15.284 ccw(c15.29,15.008) JP2.1@15.29,15.496 ; JP2.1@15.692,15.707 cw(c15.29,15.983) JP2.1@15.29,15.496 ; JP2.1@15.29,15.496 JP2.1@16,15.496
VDD3V3: C2.2 C4.1 C9.1 C10.2 JP15.1 LED1.1 R1.2 R3.2 R4.2 U1.1 U1.3 U1.4 U1.11 U1.17 U1.29 U1.30 U2.8 | length 69
  Top Layer w0.254: U1.4 5.06,11.067 5.045,11.082 5.035,11.092 5.035,11.474 5.118,11.557 5.71,11.557 U1.3 ; 6.706,5.838 6.683,5.86 6.683,6.744 7.47,7.531 U1.11 ; U1.30@7.468,13.592 cw(c7.81,13.592) 7.568,13.833 ; U1.30 7.47,13.735 7.785,14.051 v1(7.785,14.44) ; U1.29@7.968,13.591 cw(c8.356,13.591) 8.082,13.866 ; U1.29 7.97,13.755 8.409,14.194 v1(8.409,14.491) ; 8.118,13.903 ccw(c7.586,14.435) v1@8.337,14.486 ; U2.8@8.208,5.965 U2.8@9.502,5.965 ; R1.2@9.134,15.565 v1(9.677,15.565) ; R1.2@9.198,15.386 cw(c9.63,14.955) v1@9.63,15.565 ; U2.8 11.002,5.838 ; U2.8@10.616,5.766 ccw(c10.761,6.056) 10.99,5.826 ; U1.17 10.974,9.066 11.24,8.801 11.24,6.076 ; U2.8@10.73,5.993 ccw(c10.927,6.388) 11.239,6.076 ; U2.8@10.79,5.733 cw(c11.002,5.571) 11.002,5.838 ; U2.8@10.79,5.943 ccw(c11.002,6.105) 11.002,5.838 ; 11.002,5.838 11.24,6.076
  Top Layer w0.381: R4.2@3.254,9.833 cw(c3.605,9.833) R4.2@3.357,10.081 ; 3.97,10.695 cw(c4.206,10.458) C4.1@4.206,10.792 ; 4.181,8.43 4.181,8.812 3.204,9.789 3.204,9.928 4.15,10.874 4.837,10.874 5.045,11.082
  Top Layer w0.508: C10.2@3.831,7.687 ccw(c3.217,8.43) 4.181,8.43 4.181,6.716 ; C10.2@3.836,7.389 cw(c3.289,6.685) 4.181,6.685 ; v1@4.81,7.142 ccw(c5.557,7.142) v1@5.029,6.614 ; v1@4.91,7.113 cw(c4.181,7.582) 4.181,6.716 ; U2.8 6.706,5.838 5.805,5.838 4.928,6.716 v1(4.864,6.716) 4.181,6.716 ; R3.2 13.909,6.139 13.914,6.134 v1(13.923,6.134)
  Top Layer w0.762: v1(11.924,17.515) cw(c11.932,17.515) 11.932,17.523 LED1.1
  Power w0.152: v1(9.677,15.565) 11.628,17.515 ; v1@9.677,15.689 ccw(c9.677,15.988) 9.889,15.776 ccw(c10.1,15.565) v1@9.801,15.565 ; v1@11.836,17.428 ccw(c11.628,17.223) 11.628,17.515 ; v1@11.836,17.602 cw(c11.628,17.808) 11.628,17.515 ; v1(11.924,17.515) 11.628,17.515
  Power w0.254: 4.966,5.88 13.669,5.88 v1(13.923,6.134)
  Power w0.508: 4.877,8.533 5.533,9.189 5.533,14.576 5.715,14.757 6.883,14.757 7.15,14.491 v1(8.409,14.491) ; 5.533,14.382 cw(c6.054,14.382) v1@5.686,14.75 ; v1@8.409,14.437 ccw(c8.409,14.793) 8.661,14.541 ; 8.611,14.491 v1@9.681,15.561
  Power w0.762: JP15.1@0,1.496 2.22,1.496 4.877,4.153 4.877,8.533
  other v1: 4.864,7.142 4.864,7.569 5.724,14.712
pads on no net: U1.5

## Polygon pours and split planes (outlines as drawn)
GND on Top Layer "Top-GND-Polygon" (solid, remove dead copper, pour order 7): 15.875,17.777 15.875,0.125 0.125,0.125 0.125,17.777
GND on GND "Top-GND-Polygon" (solid, remove dead copper, pour order 6): 15.875,17.98 15.875,0.125 0.125,0.125 0.125,17.98
GND on Bottom Layer "Bottom-GND-Polygon" (solid, remove dead copper, pour order 8): 15.75,17.98 15.75,0.25 0.25,0.25 0.25,17.98

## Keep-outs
Keep-Out Layer:
  the board outline again, w0.127

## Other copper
Top Layer:
  rectangle net VDD3V3: 4.181,6.716 5.142,9.074
  rectangle net VDD3V3: 5.474,12.578 5.982,14.986
  rectangle net GND: 0.807,17.413 1.433,18.894

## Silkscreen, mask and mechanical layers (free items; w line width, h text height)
Top Overlay:
  circle w0.381: c0.495,16.51 r0.18
  text "ESP-S Series" at 12.662,1.499 h1.5 r90
Bottom Overlay:
  text "RST" at 3.962,15.074 h1.5
  text "TXD0" at 14.021,15.074 h1.5
  text "ADC" at 4.014,13.147 h1.5
  text "RXD0" at 14.021,13.079 h1.5
  text "EN" at 3.218,11.129 h1.5
  text "IO5" at 14.021,11.083 h1.5
  text "IO16" at 4.653,9.138 h1.5
  text "IO4" at 14.021,9.088 h1.5
  text "IO14" at 4.675,7.132 h1.5
  text "IO0" at 14.021,7.093 h1.5
  text "IO12" at 4.632,5.126 h1.5
  text "IO2" at 14.021,5.098 h1.5
  text "IO13" at 4.635,3.119 h1.5
  text "IO15" at 14.021,3.103 h1.5
  text "VCC" at 4.017,1.11 h1.5
  text "GND" at 14.021,1.107 h1.5
  text "ESP-12S" at 7.074,1.08 h1.5 r270
  text "AI Thinker" at 8.382,1.054 h1.5 r270
Top Solder:
  lines w0.6: 1.147,0.646 1.147,16.366 2.502,16.366 ; 1.165,0.646 14.847,0.646 14.847,16.346 4.232,16.364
